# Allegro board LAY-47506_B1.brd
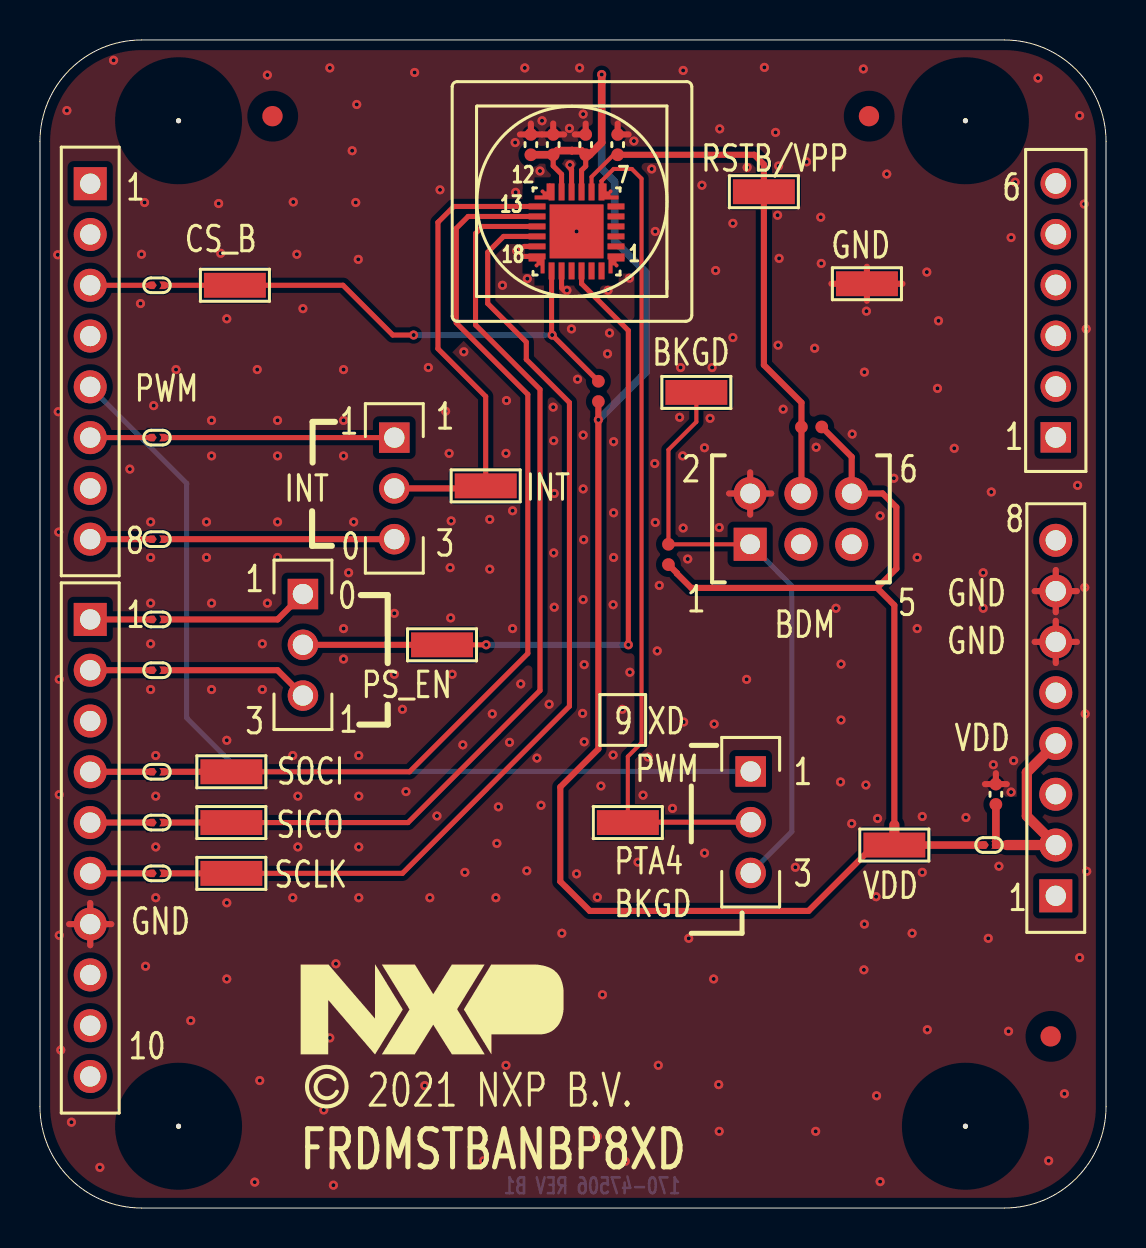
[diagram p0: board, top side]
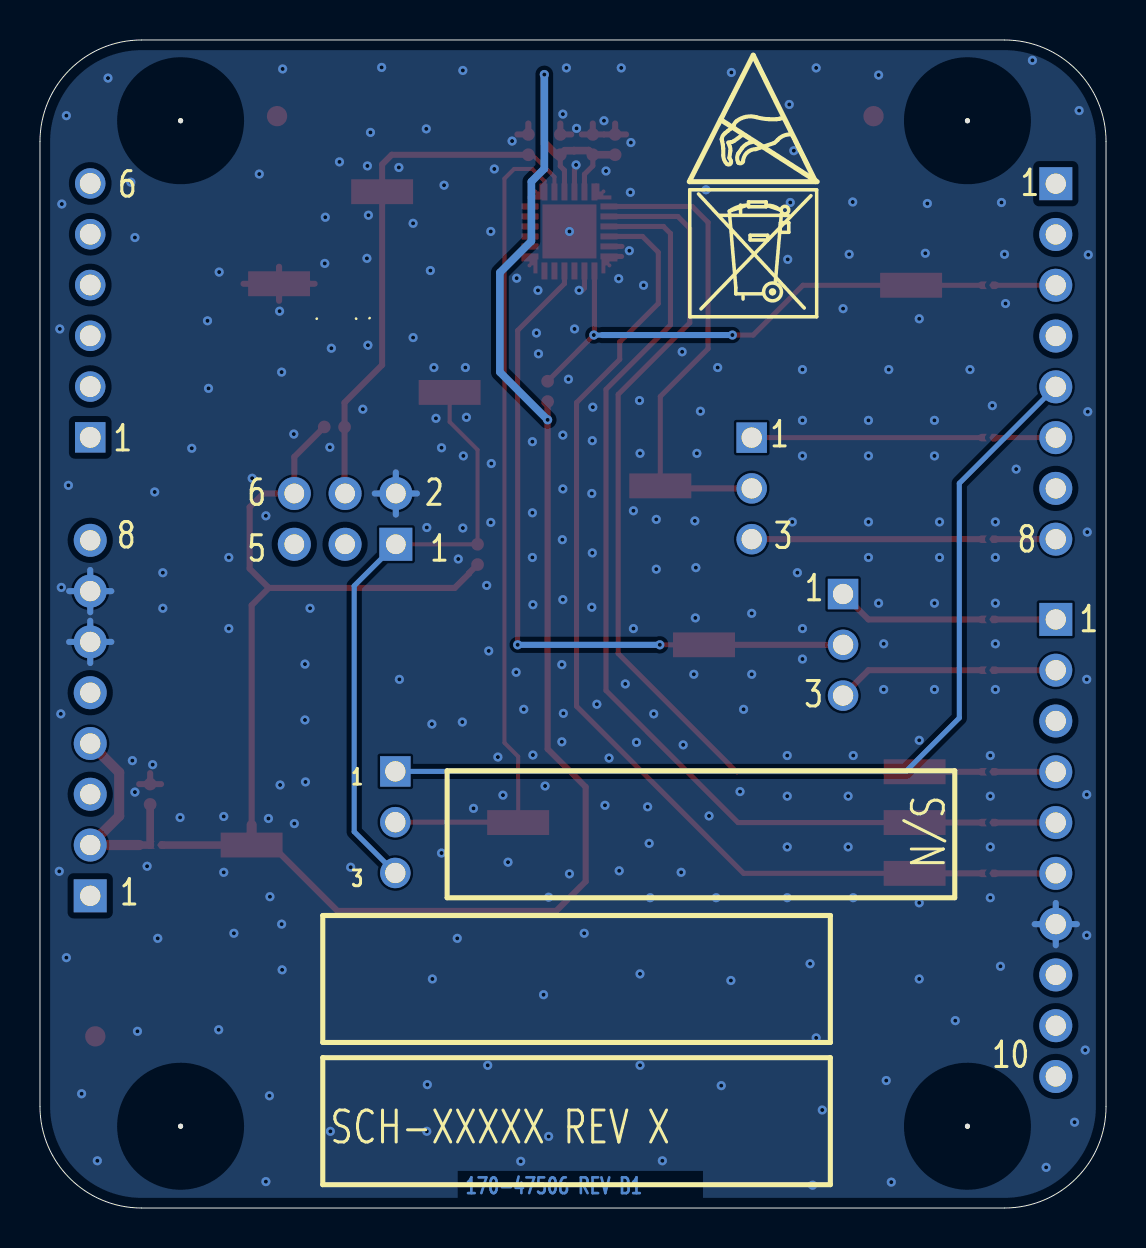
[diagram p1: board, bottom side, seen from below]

Outline 53.34 x 58.42 mm; copper layers: TOP, BOTTOM. Coordinates in mm from the lower left corner of the outline.
Outline path: 0,53.34 0,5.08 arc(1.49,1.49) 5.08,0 48.26,0 arc(51.85,1.49) 53.34,5.08 53.34,53.34 arc(51.85,56.93) 48.26,58.42 5.08,58.42 arc(1.49,56.93) 0,53.34

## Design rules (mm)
constraint set DEFAULT: min track width 0.203
nets with their own width: min track width 0.305; nets N16645673 VDD

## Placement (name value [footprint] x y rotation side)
C1  0.1uF  [CC0402_25]  24.56 53.19 90 top
C2  100pF  [CC0402_25]  25.68 53.19 90 top
C3  100pF  [CC0402_25]  27.3 53.19 90 top
C4  0.1uF  [CC0402_25]  28.91 53.19 90 top
C5  2.2UF  [CC0402_25]  47.83 20.69 90 top
J1  HDR TH 1X3  [HDR103]  17.73 38.53 0 top
J2  HDR TH 1X3  [HDR103]  13.16 30.71 0 top
J3  SKT_1X8  [CON_SKT1X8_TH]  2.51 51.23 0 top
J4  SKT_1X6  [CON_SKT1X6_TH]  50.83 38.54 180 top
J5  SKT_1X10  [CON_SKT1X10_TH]  2.51 29.44 0 top
J6  SKT_1X8  [CON_SKT1X8_TH]  50.83 15.61 180 top
J7  HDR 2X3  [HDR203_M20]  38.07 34.47 90 top
J8  HDR TH 1X3  [HDR103]  35.56 21.84 0 top
NOREF  -  []  25.15 50.84 0 top
NOREF#2  -  []  28.41 18.65 0 top
NOREF#3  -  [unnamed#2]  50.57 8.59 180 top
NOREF#4  -  [unnamed#2]  6.93 4.09 0 top
NOREF#5  -  []  5.6 19.28 0 top
NOREF#6  -  []  6.93 4.09 0 top
NOREF#7  -  []  23.3 35.49 90 top
NOREF#8  -  []  10.75 45.53 90 top
NOREF#9  -  []  6.93 54.38 0 top
NOREF#10  -  []  25.6 50.82 0 top
NOREF#11  -  []  24.85 47.14 90 top
NOREF#12  -  []  43.75 17.53 90 top
NOREF#13  -  [unnamed#2]  46.3 54.38 0 top
NOREF#14  -  [unnamed#2]  41.48 54.61 180 top
NOREF#15  -  []  20.85 50.84 0 top
NOREF#16  -  []  30.41 18.65 90 top
NOREF#17  -  []  27.6 50.82 0 top
NOREF#18  -  []  14.35 6.05 0 top
NOREF#19  -  []  37.22 50.21 90 top
NOREF#20  -  []  229.59 -115.29 0 top
NOREF#21  -  []  5.6 26.9 0 top
NOREF#22  -  []  8.58 21.19 0 top
NOREF#23  -  []  6.93 4.09 0 top
NOREF#24  -  []  380.62 -135.13 0 top
NOREF#25  -  []  6.93 4.09 0 top
NOREF#26  -  [unnamed#2]  46.3 4.09 0 top
NOREF#27  -  []  24.87 47.59 90 top
NOREF#28  -  []  0 53.04 0 top
NOREF#29  -  []  10.58 18.65 90 top
NOREF#30  -  []  35.22 50.21 0 top
NOREF#31  -  []  41.75 17.53 0 top
NOREF#32  -  []  46.3 4.09 90 top
NOREF#33  -  []  33.84 41.42 0 top
NOREF#34  -  []  24.87 49.59 90 top
NOREF#35  -  []  19.12 27.54 0 top
NOREF#36  -  []  8.58 16.11 0 top
NOREF#37  -  []  8.75 45.53 0 top
NOREF#38  -  []  42.38 45.6 90 top
NOREF#39  -  []  5.6 33.45 0 top
NOREF#40  -  []  21.12 27.54 90 top
NOREF#41  -  [unnamed#2]  11.63 54.61 180 top
NOREF#42  -  []  -382.6 -270.51 0 top
NOREF#43  -  []  5.6 29.44 0 top
NOREF#44  -  []  24.85 50.84 90 top
NOREF#45  -  []  8.58 18.65 0 top
NOREF#46  -  []  -140.18 -38.1 0 top
NOREF#47  -  []  40.38 45.6 0 top
NOREF#48  -  []  5.6 38.53 0 top
NOREF#49  -  []  21.3 35.49 0 top
NOREF#50  -  []  6.93 4.09 0 top
NOREF#51  -  []  47.23 18.15 0 top
NOREF#52  -  []  10.58 16.11 90 top
NOREF#53  -  [unnamed#2]  6.93 54.38 0 top
NOREF#54  -  []  46.84 0 90 top
NOREF#55  -  []  1.42 56.86 0 top
NOREF#56  -  []  13.05 7.68 0 top
NOREF#57  -  []  207.59 9.47 0 top
NOREF#58  -  []  5.6 21.82 0 top
NOREF#59  -  []  10.58 21.19 90 top
NOREF#60  -  []  5.6 16.74 0 top
NOREF#61  -  []  -356.12 253.79 0 top
NOREF#62  -  []  35.84 41.42 90 top
NOREF#63  -  []  5.6 46.15 0 top
NOREF#64  -  []  39.19 8.28 180 bottom
NOREF#65  -  []  39.19 1.17 180 bottom
NOREF#66  -  []  20.83 51.33 180 bottom
NOREF#67  -  []  40.21 52.7 180 bottom
NOREF#68  -  []  7.57 21.87 0 bottom
NOREF#69  -  []  20.83 44.58 180 bottom
R1  0  [RC0402_25]  31.45 32.69 90 top
R2  0  [RC0402_25]  38.61 39.07 180 top
R3  0  [RC0402_25]  27.94 40.84 90 top
SH1  0201 SHORT  [0201_SOLDER_BLOB_JUMPER_SHORT]  5.85 46.15 0 top
SH2  0201 SHORT  [0201_SOLDER_BLOB_JUMPER_SHORT]  5.85 38.53 0 top
SH3  0201 SHORT  [0201_SOLDER_BLOB_JUMPER_SHORT]  5.85 33.45 0 top
SH4  0201 SHORT  [0201_SOLDER_BLOB_JUMPER_SHORT]  5.85 29.44 0 top
SH5  0201 SHORT  [0201_SOLDER_BLOB_JUMPER_SHORT]  5.85 26.9 0 top
SH6  0201 SHORT  [0201_SOLDER_BLOB_JUMPER_SHORT]  5.85 21.82 0 top
SH7  0201 SHORT  [0201_SOLDER_BLOB_JUMPER_SHORT]  5.85 19.28 0 top
SH8  0201 SHORT  [0201_SOLDER_BLOB_JUMPER_SHORT]  5.85 16.74 0 top
SH9  0201 SHORT  [0201_SOLDER_BLOB_JUMPER_SHORT]  47.49 18.15 0 top
TP1  0805  [TESTPOINT_122X049MIL]  42.75 18.15 0 top
TP2  0805  [TESTPOINT_122X049MIL]  41.38 46.23 0 top
TP3  0805  [TESTPOINT_122X049MIL]  9.75 46.15 0 top
TP4  0805  [TESTPOINT_122X049MIL]  9.58 16.74 0 top
TP5  0805  [TESTPOINT_122X049MIL]  9.58 19.28 0 top
TP6  0805  [TESTPOINT_122X049MIL]  9.58 21.82 0 top
TP7  0805  [TESTPOINT_122X049MIL]  32.84 40.79 180 top
TP8  0805  [TESTPOINT_122X049MIL]  36.22 50.83 0 top
TP9  0805  [TESTPOINT_122X049MIL]  22.3 36.12 0 top
TP10  0805  [TESTPOINT_122X049MIL]  20.12 28.17 0 top
TP11  0805  [TESTPOINT_122X049MIL]  29.41 19.28 0 top
U1  NBP8  [HPQFN24_0P5_4X4_EP_NSP]  26.85 48.84 180 top

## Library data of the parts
C1 C4 = CAP_NP: tolerance: 10%
C2 C3 = CAP_NP: tolerance: 5%
C5 = CAP_NP
J1 J2 J8 = CONN_HDR_3X1
J3 J6 = CONN_HDR_8X1
J4 = CONN_HDR_6X1
J5 = CONN_HDR_10X1
J7 = CONN_HDR_3X2
R1-R3 = RES: tolerance: 5%
SH1-SH9 = RES_SHORT-2
TP1-TP11 = TEST_POINT
U1 = NBP8_HQFN24P_4_ALT-NSP

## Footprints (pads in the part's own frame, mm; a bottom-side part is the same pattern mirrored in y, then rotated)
0201_SOLDER_BLOB_JUMPER_SHORT
  custom 0.095x0.095 smd: 1(-0.254,0) 2(0.33,0)
CC0402_25
  round 0.635 smd: 1(-0.508,0) 2(0.508,0)
CON_SKT1X6_TH
  rect 1.524x1.524 hole 1.041: 1(0,0)
  round 1.524 hole 1.041: 2(0,-2.54) 3(0,-5.08) 4(0,-7.62) 5(0,-10.16) 6(0,-12.7)
CON_SKT1X8_TH
  rect 1.651x1.651 hole 1.016: 1(0,0)
  round 1.651 hole 1.016: 2(0,-2.54) 3(0,-5.08) 4(0,-7.62) 5(0,-10.16) 6(0,-12.7) 7(0,-15.24) 8(0,-17.78)
CON_SKT1X10_TH
  rect 1.651x1.651 hole 1.016: 1(0,0)
  round 1.651 hole 1.016: 2(0,-2.54) 3(0,-5.08) 4(0,-7.62) 5(0,-10.16) 6(0,-12.7) 7(0,-15.24) 8(0,-17.78) 9(0,-20.32) 10(0,-22.86)
HDR103
  rect 1.524x1.524 hole 1.016: 1(0,0)
  round 1.524 hole 1.016: 2(0,-2.54) 3(0,-5.08)
HDR203_M20
  rect 1.651x1.651 hole 0.991: 1(-1.27,2.54)
  round 1.651 hole 0.991: 2(1.27,2.54) 3(-1.27,0) 4(1.27,0) 5(-1.27,-2.54) 6(1.27,-2.54)
HPQFN24_0P5_4X4_EP_NSP
  custom 0.2x0.2 smd: (-2,1.7) (-1.7,-2) (1.7,-2) (2,1.7)
  rect 0.85x0.3 smd: 1(-1.975,1.25) 2(-1.975,0.75) 3(-1.975,0.25) 4(-1.975,-0.25) 5(-1.975,-0.75) 6(-1.975,-1.25) 13(1.975,-1.25) 14(1.975,-0.75) 15(1.975,-0.25) 16(1.975,0.25) 17(1.975,0.75) 18(1.975,1.25)
  rect 0.3x0.85 smd: 7(-1.25,-1.975) 8(-0.75,-1.975) 9(-0.25,-1.975) 10(0.25,-1.975) 11(0.75,-1.975) 12(1.25,-1.975) 19(1.25,1.975) 20(0.75,1.975) 21(0.25,1.975) 22(-0.25,1.975) 23(-0.75,1.975) 24(-1.25,1.975)
  rect 2.7x2.7 smd: 25(0,0)
RC0402_25
  round 0.635 smd: 1(-0.508,0) 2(0.508,0)
TESTPOINT_122X049MIL
  rect 3.099x1.245 smd: 1(0,0)
unnamed#2
  round 1.016 smd: (0,0)

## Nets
GND: C1.2 C2.2 C3.2 C4.2 C5.2 J5.7 J6.6 J6.7 J7.2 TP2.1 U1.10 U1.17 U1.18 U1.20 U1.25
VDD: C1.1 C2.1 C3.1 J7.6(B3) R1.1 R2.1 R3.1 SH9.1 TP1.1 U1.9(VDDA) U1.11
BKGD: J7.1 J8.3 R1.2 TP7.1
CS_B: R3.2 SH1.2 TP3.1 U1.19
INT: J1.2 TP9.1 U1.13
INT0: J1.1 SH2.2
INT1: J1.3 SH3.2
PS_EN: J2.2 TP10.1 U1.22
PS_EN0: J2.1 SH4.2
PS_EN1: J2.3 SH5.2
PTA4: J8.2 TP11.1 U1.7
PWM: J3.5 J8.1
RSTB/VPP: C4.1 J7.4 R2.2 TP8.1 U1.8
SCLK: SH8.2 TP4.1 U1.16
SICO: SH7.2 TP5.1 U1.15
SOCI: SH6.2 TP6.1 U1.14
N16645673: C5.1 J6.2 J6.4 SH9.2
N16648755: J3.3 SH1.1
N16660945: J5.4 SH6.1
N16660985: J5.5 SH7.1
N16661025: J5.6 SH8.1
N16669684: J3.8 SH3.1
N16670698: J5.1 SH4.1
N16670702: J5.2 SH5.1
N16670795: J3.6 SH2.1

Pads without a net: J3 1 2 4 7; J4 1 2 3 4 5 6; J5 3 8 9 10; J6 1 3 5 8; J7 3 5; U1 1 2 3 4 5 6 12 21 23 24

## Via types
v1: diameter 0.457, hole 0.203, TOP to BOTTOM, 270 vias
v2: diameter 0.457, hole 0.206, TOP to BOTTOM, 1 via

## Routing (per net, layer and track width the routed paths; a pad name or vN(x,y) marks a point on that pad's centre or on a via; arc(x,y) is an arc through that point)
GND: length 50
  TOP w0.254: U1.20 26.1,46.01 26.21,45.9 v1(26.37,45.9) ; 24.22,48.09 U1.17 ; U1.10 26.6,51.94 26.52,52.02 v1(26.52,52.17) ; 24.24,47.59 U1.18
  TOP w0.305: 1.46,14.2 J5.7 ; J5.7 2.51,15.25 ; J5.7 3.57,14.2 ; J5.7 2.51,13.14 ; C2.2 25.68,54.24 ; C2.2 25.13,53.7 ; C2.2 26.23,53.7 ; TP2.1 41.38,47.08 ; TP2.1 39.6,46.23 ; TP2.1 41.38,45.38 ; TP2.1 43.16,46.23 ; 50.83,27.26 J6.6 ; J6.6 51.88,28.31 ; J6.6 50.83,29.37 ; J6.6 49.77,28.31 ; 50.83,29.8 J6.7 ; J6.7 49.77,30.85 ; J6.7 50.83,31.91 ; J6.7 51.88,30.85 ; 35.53,34.68 J7.2 ; J7.2 36.59,35.74 ; J7.2 34.48,35.74 ; J7.2 35.53,36.79 ; C1.2 24.56,54.24 ; C1.2 25.11,53.7 ; C1.2 24.02,53.7 ; C5.2 47.83,21.75 ; C5.2 47.28,21.2 ; C5.2 48.37,21.2 ; 28.91,54.24 C4.2 29.45,53.7 ; 27.3,54.24 C3.2 26.76,53.7
  BOTTOM w0.305: J6.7 51.88,30.85 ; J6.7 49.77,30.85 ; J6.7 50.83,29.8 ; J6.7 50.83,31.91 ; J7.2 36.59,35.74 ; J7.2 35.53,36.79 ; J7.2 35.53,34.68 ; J7.2 34.48,35.74 ; 2.51,13.14 J5.7 ; J5.7 2.51,15.25 ; J5.7 1.46,14.2 ; J5.7 3.57,14.2 ; J6.6 51.88,28.31 ; J6.6 50.83,27.26 ; J6.6 49.77,28.31 ; J6.6 50.83,29.37
  vias: v1(0.89,47.68) v1(0.91,39.83) v1(0.94,33.81) v1(0.97,26.44) v1(0.97,20.68) v1(0.97,13.64) v1(1.04,7.9) v1(1.35,54.89) v1(1.57,4.29) v1(3,2.03) v1(3.68,57.4) v1(4.5,36.96) v1(5.08,47.7) v1(5.03,45.24) v1(5.23,50.29) v1(5.28,12.09) v1(5.54,34.32) v1(5.54,32.54) v1(5.54,30.25) v1(5.54,28.22) v1(5.54,25.93) v1(5.69,40.13) v1(5.79,22.63) v1(5.79,20.6) v1(5.79,18.06) v1(5.79,15.52) v1(6.81,41.94) v1(7.54,9.37) v1(8.33,34.32) v1(8.33,32.54) v1(8.59,39.4) v1(8.59,37.62) v1(8.59,30.25) v1(8.59,25.93) v1(8.94,50.24) v1(9.04,47.75) v1(9.35,44.48) v1(9.35,23.39) v1(9.35,15.27) v1(9.35,11.46) v1(10.74,1.3) v1(10.87,41.94) v1(11,6.38) v1(11.13,28.22) v1(11.13,25.93) v1(11.38,56.67) v1(11.38,30.25) v1(11.89,39.4) v1(11.89,37.62) v1(11.89,34.32) v1(11.89,32.54) v1(12.67,50.32) v1(12.65,22.63) v1(12.65,15.52) v1(12.85,47.7) v1(12.9,20.6) v1(12.9,18.06) v1(13.16,44.98) v1(14.2,4.9) v1(14.5,57.02) v1(14.5,8.51) v1(14.68,1.14) v1(14.81,12.22) v1(15.19,41.94) v1(15.19,39.4) v1(15.19,37.62) v1(15.19,28.98) v1(15.19,27.46) v1(15.44,31.78) v1(15.62,52.88) v1(15.7,34.32) v1(15.85,55.19) v1(15.8,50.29) v1(15.93,47.45) v1(15.95,22.63) v1(15.95,20.6) v1(15.95,18.06) v1(15.95,15.52) v1(17.73,29.74) v1(17.73,26.7) v1(18.14,24.94) v1(18.31,20.83) v1(18.75,56.79) v1(18.77,11.38) v1(19.25,6.12) v1(19.43,42.04) v1(19.51,15.52) v1(19.86,19.61) v1(20.02,50.93) v1(20.29,39.85) v1(20.47,37.74) v1(20.57,34.37) v1(20.52,32.03) v1(20.55,29.51) v1(20.62,26.7) v1(21.16,23.16) v1(21.21,42.82) v1(21.26,16.79) v1(22.2,2.36) v1(22.5,34.44) v1(22.5,31.95) v1(22.63,24.71) v1(22.86,18.24) v1(22.81,15.52) v1(22.94,20.07) v1(23.14,46.15) v1(23.34,40.39) v1(23.32,37.74) v1(23.32,11.71) v1(23.32,7.14) v1(23.5,23.29) v1(23.65,34.87) v1(23.65,28.98) v1(23.77,53.29) v1(23.8,50.8) v1(23.85,47.88) v1(24.05,26.21) v1(24.26,57.02) v1(24.38,46.48) v1(24.36,16.87) v1(24.87,22.5) v1(25.02,51.87) v1(25.07,20.14) v1(25.12,54.38) v1(25.48,25.2) v1(25.68,40.06) v1(25.7,38.38) v1(25.73,35.74) v1(25.7,32.77) v1(25.73,30.05) v1(26.11,13.74) v1(26.49,54) v1(26.59,43.97) v1(26.85,16.71) v1(26.9,41.45) v1(27,57.02) v1(27.18,54.71) v1(27.18,38.66) v1(27.18,35.97) v1(27.18,30.43) v1(27.15,24.74) v1(27.2,33.43) v1(27.23,27.18) v1(27.23,23.32) v1(27.89,15.54) v1(27.89,3.58) v1(28.07,21.11) v1(28.14,10.67) v1(28.42,45.9) v1(28.4,42.72) v1(28.5,43.76) v1(28.68,30.18) v1(28.68,22.66) v1(28.7,38.33) v1(28.7,34.77) v1(28.7,32.54) v1(29.13,24.94) v1(29.29,2.34) v1(29.49,46.51) v1(29.51,26.8) v1(29.72,53.37) v1(29.92,17.3) v1(30.18,20.65) v1(30.43,22.56) v1(30.61,51.97) v1(30.76,37.24) v1(30.78,48.84) v1(30.78,34.29) v1(30.89,27.86) v1(30.94,7.14) v1(30.99,31.14) v1(31.65,19.99) v1(32.05,42.04) v1(32,39.55) v1(32.18,56.9) v1(32.16,37.62) v1(32.18,34.01) v1(32.21,24.31) v1(32.41,32.46) v1(32.46,13.49) v1(33.12,51.16) v1(33.25,38.02) v1(33.25,17.75) v1(33.53,39.5) v1(33.63,42.04) v1(33.73,24.21) v1(33.71,11.46) v1(33.81,46.89) v1(33.96,6.17) v1(34.01,53.97) v1(33.99,34.04) v1(33.99,3.84) v1(34.67,49.25) v1(34.67,43.54) v1(35.38,52.04) v1(35.36,26.44) v1(36.25,57.05) v1(36.8,53.8) v1(36.96,52.12) v1(36.91,49.66) v1(36.98,47.5) v1(36.93,43.15) v1(37.19,39.95) v1(37.8,17.04) v1(38.35,52.32) v1(38.76,43) v1(38.84,38.05) v1(38.81,3.84) v1(39.07,49.56) v1(39.09,47.24) v1(39.83,30) v1(40.08,27.2) v1(40.08,24.41) v1(40.06,21.31) v1(40.64,38.71) v1(40.61,19.23) v1(41.2,56.97) v1(41.25,41.81) v1(41.25,14.2) v1(41.22,11.91) v1(41.35,44.86) v1(41.33,21.16) v1(41.83,15.57) v1(41.86,5.61) v1(41.91,19.48) v1(42.04,34.62) v1(42.04,1.32) v1(42.37,51.71) v1(42.72,36.5) v1(43.64,13.74) v1(43.89,32.54) v1(43.89,28.98) v1(44.15,19.58) v1(44.15,16.79) v1(44.37,46.81) v1(44.4,8.92) v1(44.96,44.37) v1(44.91,41) v1(45.75,38) v1(46.33,19.53) v1(47.19,31.78) v1(47.19,30) v1(47.45,13.49) v1(47.6,35.81) v1(47.7,22.17) v1(47.98,17.09) v1(48.46,8.84) v1(48.59,48.54) v1(48.59,20.8) v1(48.72,22.38) v1(48.79,51.31) v1(49.94,56.52) v1(50.47,2.36) v1(51.26,5.71) v1(51.92,36.14) v1(52.02,54.64) v1(52.02,12.52) v1(52.25,50.22) v1(52.27,31.04) v1(52.35,43.97) v1(52.3,24.71) v1(52.37,16.84) v2(26.85,48.84)
VDD: length 113.6
  TOP w0.254: C3.1 27.3,52.11 27.1,51.9 U1.9 ; U1.11 26.1,51.7 25.68,52.12 C2.1 ; 42.74,18.16 TP1.1
  TOP w0.305: 42.75,19.16 42.75,30.15 41.88,31.01 ; 41.88,31.01 32.59,31.01 31.87,31.73 31.87,31.76 R1.1 ; 41.88,31.01 42.85,31.98 42.85,35.05 42.16,35.74 J7.6 40.61,37.57 R2.1 ; R3.1 v1(27.94,39.42) 27.94,22.96 26.04,21.06 26.04,16.33 27.51,14.86 38.46,14.86 41.76,18.16 42.74,18.16
  TOP w0.381: C1.1 C2.1 25.89,52.89 26.62,52.89 26.62,52.88 27.08,52.88 27.28,52.68 C3.1 27.5,52.68 28.11,53.28 v1(28.11,56.69) ; SH9.1 TP1.1
  TOP w0.508: TP1.1 42.75,19.16
  BOTTOM w0.381: v1(27.94,39.42) 30.33,41.81 30.33,46.79 28.75,48.36 28.75,51.33 28.11,51.98 v1(28.11,56.69)
BKGD: length 30.4
  TOP w0.203: J7.1 R1.2 31.45,37.92 32.84,39.32 TP7.1
  BOTTOM w0.254: J8.3 35.56,16.76 37.62,18.82 37.62,31.12 J7.1
CS_B: length 27
  TOP w0.254: U1.19 25.6,43.69 v1(25.63,43.66) R3.2 ; v1(18.69,43.66) 17.65,43.66 15.16,46.15 TP3.1 SH1.2
  BOTTOM w0.254: 25.2,43.66 v1(25.63,43.66)
  BOTTOM w0.305: v1(18.69,43.66) 25.2,43.66
INT: length 24.2
  TOP w0.254: TP9.1 22.3,40.59 19.91,42.98 19.91,49.3 20.71,50.09 U1.13
  TOP w0.305: J1.2 22.3,35.99 TP9.1
INT0: length 11.5
  TOP w0.254: J1.1 SH2.2
INT1: length 11.5
  TOP w0.254: SH3.2 6.2,33.45
  TOP w0.305: 6.2,33.45 J1.3
PS_EN: length 36
  TOP w0.254: U1.22 27.1,46.23 29.44,43.89 v1(29.44,28.17) ; v1(22.33,28.17) TP10.1
  TOP w0.305: J2.2 TP10.1
  BOTTOM w0.305: v1(22.33,28.17) v1(29.44,28.17)
PS_EN0: length 7.5
  TOP w0.254: SH4.2 6.2,29.44
  TOP w0.305: 6.2,29.44 11.89,29.44 J2.1
PS_EN1: length 7.5
  TOP w0.254: SH5.2 6.2,26.9
  TOP w0.305: 6.2,26.9 11.89,26.9 J2.3
PTA4: length 41.6
  TOP w0.203: U1.7 28.1,51.36 28.09,51.36 28.7,51.97 29.62,51.97 30.1,51.49 30.1,23.27 29.41,22.58 TP11.1
  TOP w0.254: J8.2 29.43,19.3 TP11.1
PWM: length 47.9
  BOTTOM w0.254: J8.1 10.01,21.84 7.34,24.51 7.34,36.25 J3.5
RSTB/VPP: length 27.3
  TOP w0.203: C4.1 28.7,52.68 27.6,51.58 U1.8
  TOP w0.305: J7.4 38.1,35.76 R2.2 38.1,40.28 36.22,42.16 TP8.1 36.22,52.2 35.74,52.68 C4.1
SCLK: length 51
  TOP w0.254: U1.16 23.19,48.59 22.4,47.8 22.4,45.24 24.33,43.31 24.33,42.44 26.49,40.28 26.49,25.1 18.14,16.74 TP4.1 ; SH8.2 6.2,16.74
  TOP w0.305: 6.2,16.74 TP4.1
SICO: length 49
  TOP w0.254: SH7.2 6.2,19.28 ; U1.15 22.14,49.09 21.79,48.74 21.79,44.17 25.02,40.94 25.02,25.88 18.41,19.28 TP5.1
  TOP w0.305: 6.2,19.28 TP5.1
SOCI: length 47.7
  TOP w0.254: SH6.2 6.2,21.82 ; U1.14 21.43,49.59 20.83,49 20.83,44.27 24.41,40.69 24.41,27.74 18.49,21.82 TP6.1
  TOP w0.305: 6.2,21.82 TP6.1
N16645673: length 11.3
  TOP w0.381: 47.83,18.17 SH9.2 ; 47.83,18.17 47.83,18.15 48.37,18.15 ; 47.83,18.17 C5.1
  TOP w0.508: J6.4 49.38,21.79 49.38,19.6 J6.2 48.37,18.15
N16648755: length 3.1
  TOP w0.254: SH1.1 J3.3
N16660945: length 3.1
  TOP w0.254: SH6.1 5.51,21.82
  TOP w0.305: 5.51,21.82 J5.4
N16660985: length 3.1
  TOP w0.254: SH7.1 5.51,19.28
  TOP w0.305: 5.51,19.28 J5.5
N16661025: length 3.1
  TOP w0.254: SH8.1 5.51,16.74
  TOP w0.305: 5.51,16.74 J5.6
N16669684: length 3.1
  TOP w0.254: SH3.1 5.51,33.45
  TOP w0.305: 5.51,33.45 J3.8
N16670698: length 3.1
  TOP w0.254: SH4.1 5.51,29.44
  TOP w0.305: 5.51,29.44 J5.1
N16670702: length 3.1
  TOP w0.254: SH5.1 5.51,26.9
  TOP w0.305: 5.51,26.9 J5.2
N16670795: length 3.1
  TOP w0.254: SH2.1 J3.6

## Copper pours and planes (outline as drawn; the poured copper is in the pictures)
GND on TOP: 5.08,0.51 1.85,1.85 0.51,5.08 0.51,53.34 1.85,56.57 5.08,57.91 48.26,57.91 51.49,56.57 52.83,53.34 52.83,5.08 51.49,1.85 48.26,0.51 ; 1 cut-out
GND on BOTTOM: 5.08,0.51 1.85,1.85 0.51,5.08 0.51,53.34 1.85,56.57 5.08,57.91 48.26,57.91 51.49,56.57 52.83,53.34 52.83,5.08 51.49,1.85 48.26,0.51

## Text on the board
BOTTOM: 170-47506 REV B1 | 5 OF 8 | L2 SS
Board Geometry/Soldermask Bottom: 6 OF 8 | SECONDARY SOLDERMASK
Ref Des/Silkscreen Bottom: 7 OF 8 | SECONDARY SILKSCREEN
User.Comments: 1 OF 1 | TEST PROBE | 1/1 | 1 | 2
TOP: 4 OF 8 | L1 PS
Board Geometry/Soldermask Top: 3 OF 8 | PRIMARY SOLDERMASK
Ref Des/Silkscreen Top: GND | PWM | CS_B | SCLK | SICO | SOCI | INT | 0 | 1 | PS_EN | 9 XD | PTA4 | BKGD | RSTB/VPP | BDM | VDD | 2 OF 8 | PRIMARY SILKSCREEN | FRDMSTBANBP8XD
XSECTION_CHART: 23. THIS BOARD USES VIA-IN-PAD: SEE FAB_VIAFILL. | A.ALL VIAS USING X.1 DRILL SIZES ARE TO BE FILLED WITH NON-CONDUCTIVE VIA FILL. | C.DIMPLE OR PROTRUSION ON VIA-IN-PAD MUST BE NO GREATER THAN .001'. | B.OVERPLATE THE FILLED VIA AND APPLY FINISH METAL TREATMENT. | LACKWERKE-PETERS PP2795 OR EQUIVALENT AND MADE PLANAR TO THE PADS. | INTENTIONAL 9 SHORTS AT: | Location           RefDes      Net 1            Net 2 | (-42.50 598.00)    SH7       N16660985     &  MISO | (-42.50 498.00)    SH8       N16661025     &  SCLK | (-42.50 698.00)    SH6       N16660945     &  MOSI/WAKE_UP | (-42.50 998.00)    SH4       N16670698     &  PS_EN0 | (-42.50 898.00)    SH5       N16670702     &  PS_EN1 | (-42.50 1156.01)   SH3       N16669684     &  INT1 | (-42.50 1356.01)   SH2       N16670795     &  INT0 | (-42.50 1656.01)   SH1       N16648755     &  SS_B | (1596.50 553.74)   SH9       VDD           &  N16645673 | 16 | 17 | 23 | 8 | 22. | *  SURFACE - AIR 0 MIL | *  DIELECTRIC - DRY_FILM_MASK 3 MIL | L1 TOP CONDUCTOR - 1OZ_COPPER 1.2 MIL | *  DIELECTRIC - FR-4 54 MIL | L2 BOTTOM CONDUCTOR - 1OZ_COPPER 1.2 MIL | DESIGN CROSS SECTION CHART | ___________________________ | TOTAL THICKNESS 62.4 MIL | 1-2
DIMENSION: PRIMARY DATUM | GRID ORIGIN
BODY_CENTER: 1 OF 8 | PRIMARY PASTEMASK
PASTEMASK_BOTTOM: 8 OF 8 | SECONDARY PASTEMASK
User.9: 2 OF 8 | 7 OF 8 | SECONDARY SILKSCREEN | PRIMARY SILKSCREEN
User.10: 1 | 8
User.20: 02-09-21 | LAY UPDATES AND PROD RELEASE | V.R. | B
User.24: FIGURE | FINISHED_SIZE | 8.0 | 8.1 | 39.0 | 40.0 | 41.0 | 125.0 | DRILL CHART: TOP to BOTTOM | ALL UNITS ARE IN MILS | TOLERANCE_DRILL | +0.0/-8.0 | +0.0/-8.1 | +3.0/-3.0 | +2.0/-2.0 | PLATED | NON-PLATED | QTY | 270 | 1 | 6 | 35 | 4
